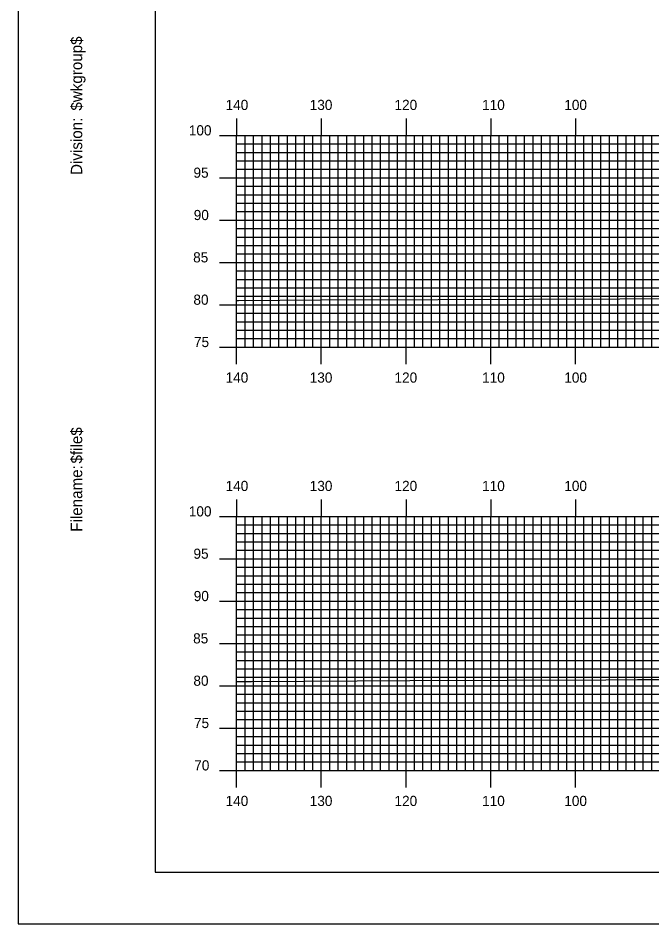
# Model space of a CAD drawing. Extents: x 1757069 to 1757412, y 442591 to 442811.
# Drawn here: x 1757068.8 to 1757143.6, y 442590.5 to 442697.5 of the extents above; entities that cross this region are included whole.
import ezdxf

# ---------------------------------------------------------------- set-up
doc = ezdxf.new("R2010")
doc.units = 0
for name, color, linetype in [('BORDER', 7, 'Continuous'), ('H_V ANNOTATION', 7, 'Continuous'), ('MAJOR', 7, 'Continuous'), ('MINOR', 7, 'Continuous'), ('PLOT BOUNDARY', 7, 'Continuous'), ('S_Roadway_Centerline', 7, 'Continuous')]:
    doc.layers.add(name, color=color, linetype=linetype)

msp = doc.modelspace()

# ---------------------------------------------------------------- linework, layer by layer
at = {"layer": 'BORDER'}
msp.add_lwpolyline([(1757085, 442596.67), (1757405, 442596.67), (1757405, 442806.67), (1757085, 442806.67)], close=True, dxfattribs=at)
at = {"layer": 'MAJOR'}
for p, q in [((1757094.6, 442685.67), (1757094.6, 442683.67)), ((1757104.6, 442685.67), (1757104.6, 442683.67)), ((1757114.6, 442685.67), (1757114.6, 442683.67)), ((1757124.6, 442685.67), (1757124.6, 442683.67)), ((1757134.6, 442685.67), (1757134.6, 442683.67)), ((1757092.59, 442683.67), (1757094.6, 442683.67)), ((1757094.6, 442683.67), (1757374.6, 442683.67)), ((1757094.6, 442658.67), (1757094.6, 442683.67)), ((1757094.6, 442658.67), (1757094.6, 442683.67)), ((1757094.6, 442683.67), (1757374.6, 442683.67)), ((1757104.6, 442658.67), (1757104.6, 442683.67)), ((1757114.6, 442658.67), (1757114.6, 442683.67)), ((1757124.6, 442658.67), (1757124.6, 442683.67)), ((1757134.6, 442658.67), (1757134.6, 442683.67)), ((1757092.59, 442678.67), (1757094.6, 442678.67)), ((1757094.6, 442678.67), (1757374.6, 442678.67)), ((1757092.59, 442673.67), (1757094.6, 442673.67)), ((1757094.6, 442673.67), (1757374.6, 442673.67)), ((1757092.59, 442668.67), (1757094.6, 442668.67)), ((1757094.6, 442668.67), (1757374.6, 442668.67)), ((1757092.59, 442663.67), (1757094.6, 442663.67)), ((1757094.6, 442663.67), (1757374.6, 442663.67)), ((1757092.59, 442658.67), (1757094.6, 442658.67)), ((1757094.6, 442658.67), (1757374.6, 442658.67)), ((1757094.6, 442658.67), (1757374.6, 442658.67)), ((1757094.6, 442656.66), (1757094.6, 442658.67)), ((1757104.6, 442656.66), (1757104.6, 442658.67)), ((1757114.6, 442656.66), (1757114.6, 442658.67)), ((1757124.6, 442656.66), (1757124.6, 442658.67)), ((1757134.6, 442656.66), (1757134.6, 442658.67)), ((1757094.6, 442640.67), (1757094.6, 442638.67)), ((1757104.6, 442640.67), (1757104.6, 442638.67)), ((1757114.6, 442640.67), (1757114.6, 442638.67)), ((1757124.6, 442640.67), (1757124.6, 442638.67)), ((1757134.6, 442640.67), (1757134.6, 442638.67)), ((1757092.59, 442638.67), (1757094.6, 442638.67)), ((1757094.6, 442638.67), (1757374.6, 442638.67)), ((1757094.6, 442608.67), (1757094.6, 442638.67)), ((1757094.6, 442608.67), (1757094.6, 442638.67)), ((1757094.6, 442638.67), (1757374.6, 442638.67)), ((1757104.6, 442608.67), (1757104.6, 442638.67)), ((1757114.6, 442608.67), (1757114.6, 442638.67)), ((1757124.6, 442608.67), (1757124.6, 442638.67)), ((1757134.6, 442608.67), (1757134.6, 442638.67)), ((1757092.59, 442633.67), (1757094.6, 442633.67)), ((1757094.6, 442633.67), (1757374.6, 442633.67)), ((1757092.59, 442628.67), (1757094.6, 442628.67)), ((1757094.6, 442628.67), (1757374.6, 442628.67)), ((1757092.59, 442623.67), (1757094.6, 442623.67)), ((1757094.6, 442623.67), (1757374.6, 442623.67)), ((1757092.59, 442618.67), (1757094.6, 442618.67)), ((1757094.6, 442618.67), (1757374.6, 442618.67)), ((1757092.59, 442613.67), (1757094.6, 442613.67)), ((1757094.6, 442613.67), (1757374.6, 442613.67)), ((1757092.59, 442608.67), (1757094.6, 442608.67)), ((1757094.6, 442608.67), (1757374.6, 442608.67)), ((1757094.6, 442608.67), (1757374.6, 442608.67)), ((1757094.6, 442606.66), (1757094.6, 442608.67)), ((1757104.6, 442606.66), (1757104.6, 442608.67)), ((1757114.6, 442606.66), (1757114.6, 442608.67)), ((1757124.6, 442606.66), (1757124.6, 442608.67)), ((1757134.6, 442606.66), (1757134.6, 442608.67))]:
    msp.add_line(p, q, dxfattribs=at)
at = {"layer": 'MINOR'}
for p, q in [((1757095.6, 442658.67), (1757095.6, 442683.67)), ((1757096.6, 442658.67), (1757096.6, 442683.67)), ((1757097.6, 442658.67), (1757097.6, 442683.67)), ((1757098.6, 442658.67), (1757098.6, 442683.67)), ((1757099.6, 442658.67), (1757099.6, 442683.67)), ((1757100.6, 442658.67), (1757100.6, 442683.67)), ((1757101.6, 442658.67), (1757101.6, 442683.67)), ((1757102.6, 442658.67), (1757102.6, 442683.67)), ((1757103.6, 442658.67), (1757103.6, 442683.67)), ((1757105.6, 442658.67), (1757105.6, 442683.67)), ((1757106.6, 442658.67), (1757106.6, 442683.67)), ((1757107.6, 442658.67), (1757107.6, 442683.67)), ((1757108.6, 442658.67), (1757108.6, 442683.67)), ((1757109.6, 442658.67), (1757109.6, 442683.67)), ((1757110.6, 442658.67), (1757110.6, 442683.67)), ((1757111.6, 442658.67), (1757111.6, 442683.67)), ((1757112.6, 442658.67), (1757112.6, 442683.67)), ((1757113.6, 442658.67), (1757113.6, 442683.67)), ((1757115.6, 442658.67), (1757115.6, 442683.67)), ((1757116.6, 442658.67), (1757116.6, 442683.67)), ((1757117.6, 442658.67), (1757117.6, 442683.67)), ((1757118.6, 442658.67), (1757118.6, 442683.67)), ((1757119.6, 442658.67), (1757119.6, 442683.67)), ((1757120.6, 442658.67), (1757120.6, 442683.67)), ((1757121.6, 442658.67), (1757121.6, 442683.67)), ((1757122.6, 442658.67), (1757122.6, 442683.67)), ((1757123.6, 442658.67), (1757123.6, 442683.67)), ((1757125.6, 442658.67), (1757125.6, 442683.67)), ((1757126.6, 442658.67), (1757126.6, 442683.67)), ((1757127.6, 442658.67), (1757127.6, 442683.67)), ((1757128.6, 442658.67), (1757128.6, 442683.67)), ((1757129.6, 442658.67), (1757129.6, 442683.67)), ((1757130.6, 442658.67), (1757130.6, 442683.67)), ((1757131.6, 442658.67), (1757131.6, 442683.67)), ((1757132.6, 442658.67), (1757132.6, 442683.67)), ((1757133.6, 442658.67), (1757133.6, 442683.67)), ((1757135.6, 442658.67), (1757135.6, 442683.67)), ((1757136.6, 442658.67), (1757136.6, 442683.67)), ((1757137.6, 442658.67), (1757137.6, 442683.67)), ((1757138.6, 442658.67), (1757138.6, 442683.67)), ((1757139.6, 442658.67), (1757139.6, 442683.67)), ((1757140.6, 442658.67), (1757140.6, 442683.67)), ((1757141.6, 442658.67), (1757141.6, 442683.67)), ((1757142.6, 442658.67), (1757142.6, 442683.67)), ((1757143.6, 442658.67), (1757143.6, 442683.67)), ((1757094.6, 442682.67), (1757374.6, 442682.67)), ((1757094.6, 442682.67), (1757096.6, 442682.67)), ((1757094.6, 442681.67), (1757374.6, 442681.67)), ((1757094.6, 442681.67), (1757096.6, 442681.67)), ((1757094.6, 442680.67), (1757374.6, 442680.67)), ((1757094.6, 442680.67), (1757096.6, 442680.67)), ((1757094.6, 442679.67), (1757374.6, 442679.67)), ((1757094.6, 442679.67), (1757096.6, 442679.67)), ((1757094.6, 442677.67), (1757374.6, 442677.67)), ((1757094.6, 442677.67), (1757096.6, 442677.67)), ((1757094.6, 442676.67), (1757374.6, 442676.67)), ((1757094.6, 442676.67), (1757096.6, 442676.67)), ((1757094.6, 442675.67), (1757374.6, 442675.67)), ((1757094.6, 442675.67), (1757096.6, 442675.67)), ((1757094.6, 442674.67), (1757374.6, 442674.67)), ((1757094.6, 442674.67), (1757096.6, 442674.67)), ((1757094.6, 442672.67), (1757374.6, 442672.67)), ((1757094.6, 442672.67), (1757096.6, 442672.67)), ((1757094.6, 442671.67), (1757374.6, 442671.67)), ((1757094.6, 442671.67), (1757096.6, 442671.67)), ((1757094.6, 442670.67), (1757374.6, 442670.67)), ((1757094.6, 442670.67), (1757096.6, 442670.67)), ((1757094.6, 442669.67), (1757374.6, 442669.67)), ((1757094.6, 442669.67), (1757096.6, 442669.67)), ((1757094.6, 442667.67), (1757374.6, 442667.67)), ((1757094.6, 442667.67), (1757096.6, 442667.67)), ((1757094.6, 442666.67), (1757374.6, 442666.67)), ((1757094.6, 442666.67), (1757096.6, 442666.67)), ((1757094.6, 442665.67), (1757374.6, 442665.67)), ((1757094.6, 442665.67), (1757096.6, 442665.67)), ((1757094.6, 442664.67), (1757374.6, 442664.67)), ((1757094.6, 442664.67), (1757096.6, 442664.67)), ((1757094.6, 442662.67), (1757374.6, 442662.67)), ((1757094.6, 442662.67), (1757096.6, 442662.67)), ((1757094.6, 442661.67), (1757374.6, 442661.67)), ((1757094.6, 442661.67), (1757096.6, 442661.67)), ((1757094.6, 442660.67), (1757374.6, 442660.67)), ((1757094.6, 442660.67), (1757096.6, 442660.67)), ((1757094.6, 442659.67), (1757374.6, 442659.67)), ((1757094.6, 442659.67), (1757096.6, 442659.67)), ((1757095.6, 442608.67), (1757095.6, 442638.67)), ((1757096.6, 442608.67), (1757096.6, 442638.67)), ((1757097.6, 442608.67), (1757097.6, 442638.67)), ((1757098.6, 442608.67), (1757098.6, 442638.67)), ((1757099.6, 442608.67), (1757099.6, 442638.67)), ((1757100.6, 442608.67), (1757100.6, 442638.67)), ((1757101.6, 442608.67), (1757101.6, 442638.67)), ((1757102.6, 442608.67), (1757102.6, 442638.67)), ((1757103.6, 442608.67), (1757103.6, 442638.67)), ((1757105.6, 442608.67), (1757105.6, 442638.67)), ((1757106.6, 442608.67), (1757106.6, 442638.67)), ((1757107.6, 442608.67), (1757107.6, 442638.67)), ((1757108.6, 442608.67), (1757108.6, 442638.67)), ((1757109.6, 442608.67), (1757109.6, 442638.67)), ((1757110.6, 442608.67), (1757110.6, 442638.67)), ((1757111.6, 442608.67), (1757111.6, 442638.67)), ((1757112.6, 442608.67), (1757112.6, 442638.67)), ((1757113.6, 442608.67), (1757113.6, 442638.67)), ((1757115.6, 442608.67), (1757115.6, 442638.67)), ((1757116.6, 442608.67), (1757116.6, 442638.67)), ((1757117.6, 442608.67), (1757117.6, 442638.67)), ((1757118.6, 442608.67), (1757118.6, 442638.67)), ((1757119.6, 442608.67), (1757119.6, 442638.67)), ((1757120.6, 442608.67), (1757120.6, 442638.67)), ((1757121.6, 442608.67), (1757121.6, 442638.67)), ((1757122.6, 442608.67), (1757122.6, 442638.67)), ((1757123.6, 442608.67), (1757123.6, 442638.67)), ((1757125.6, 442608.67), (1757125.6, 442638.67)), ((1757126.6, 442608.67), (1757126.6, 442638.67)), ((1757127.6, 442608.67), (1757127.6, 442638.67)), ((1757128.6, 442608.67), (1757128.6, 442638.67)), ((1757129.6, 442608.67), (1757129.6, 442638.67)), ((1757130.6, 442608.67), (1757130.6, 442638.67)), ((1757131.6, 442608.67), (1757131.6, 442638.67)), ((1757132.6, 442608.67), (1757132.6, 442638.67)), ((1757133.6, 442608.67), (1757133.6, 442638.67)), ((1757135.6, 442608.67), (1757135.6, 442638.67)), ((1757136.6, 442608.67), (1757136.6, 442638.67)), ((1757137.6, 442608.67), (1757137.6, 442638.67)), ((1757138.6, 442608.67), (1757138.6, 442638.67)), ((1757139.6, 442608.67), (1757139.6, 442638.67)), ((1757140.6, 442608.67), (1757140.6, 442638.67)), ((1757141.6, 442608.67), (1757141.6, 442638.67)), ((1757142.6, 442608.67), (1757142.6, 442638.67)), ((1757143.6, 442608.67), (1757143.6, 442638.67)), ((1757094.6, 442637.67), (1757374.6, 442637.67)), ((1757094.6, 442637.67), (1757096.6, 442637.67)), ((1757094.6, 442636.67), (1757374.6, 442636.67)), ((1757094.6, 442636.67), (1757096.6, 442636.67)), ((1757094.6, 442635.67), (1757374.6, 442635.67)), ((1757094.6, 442635.67), (1757096.6, 442635.67)), ((1757094.6, 442634.67), (1757374.6, 442634.67)), ((1757094.6, 442634.67), (1757096.6, 442634.67)), ((1757094.6, 442632.67), (1757374.6, 442632.67)), ((1757094.6, 442632.67), (1757096.6, 442632.67)), ((1757094.6, 442631.67), (1757374.6, 442631.67)), ((1757094.6, 442631.67), (1757096.6, 442631.67)), ((1757094.6, 442630.67), (1757374.6, 442630.67)), ((1757094.6, 442630.67), (1757096.6, 442630.67)), ((1757094.6, 442629.67), (1757374.6, 442629.67)), ((1757094.6, 442629.67), (1757096.6, 442629.67)), ((1757094.6, 442627.67), (1757374.6, 442627.67)), ((1757094.6, 442627.67), (1757096.6, 442627.67)), ((1757094.6, 442626.67), (1757374.6, 442626.67)), ((1757094.6, 442626.67), (1757096.6, 442626.67)), ((1757094.6, 442625.67), (1757374.6, 442625.67)), ((1757094.6, 442625.67), (1757096.6, 442625.67)), ((1757094.6, 442624.67), (1757374.6, 442624.67)), ((1757094.6, 442624.67), (1757096.6, 442624.67)), ((1757094.6, 442622.67), (1757374.6, 442622.67)), ((1757094.6, 442622.67), (1757096.6, 442622.67)), ((1757094.6, 442621.67), (1757374.6, 442621.67)), ((1757094.6, 442621.67), (1757096.6, 442621.67)), ((1757094.6, 442620.67), (1757374.6, 442620.67)), ((1757094.6, 442620.67), (1757096.6, 442620.67)), ((1757094.6, 442619.67), (1757374.6, 442619.67)), ((1757094.6, 442619.67), (1757096.6, 442619.67)), ((1757094.6, 442617.67), (1757374.6, 442617.67)), ((1757094.6, 442617.67), (1757096.6, 442617.67)), ((1757094.6, 442616.67), (1757374.6, 442616.67)), ((1757094.6, 442616.67), (1757096.6, 442616.67)), ((1757094.6, 442615.67), (1757374.6, 442615.67)), ((1757094.6, 442615.67), (1757096.6, 442615.67)), ((1757094.6, 442614.67), (1757374.6, 442614.67)), ((1757094.6, 442614.67), (1757096.6, 442614.67)), ((1757094.6, 442612.67), (1757374.6, 442612.67)), ((1757094.6, 442612.67), (1757096.6, 442612.67)), ((1757094.6, 442611.67), (1757374.6, 442611.67)), ((1757094.6, 442611.67), (1757096.6, 442611.67)), ((1757094.6, 442610.67), (1757374.6, 442610.67)), ((1757094.6, 442610.67), (1757096.6, 442610.67)), ((1757094.6, 442609.67), (1757374.6, 442609.67)), ((1757094.6, 442609.67), (1757096.6, 442609.67))]:
    msp.add_line(p, q, dxfattribs=at)
at = {"layer": 'PLOT BOUNDARY'}
msp.add_lwpolyline([(1757068.81, 442590.55), (1757408.81, 442590.55), (1757408.81, 442810.55), (1757068.81, 442810.55)], close=True, dxfattribs=at)
at = {"layer": 'S_Roadway_Centerline'}
for points in [[(1757094.6, 442664.18), (1757094.81, 442664.19), (1757104.62, 442664.24), (1757118.38, 442664.3), (1757139.82, 442664.37), (1757152.51, 442664.44), (1757175.36, 442664.55), (1757195.7, 442664.74), (1757219.61, 442665.15), (1757229.73, 442665.24), (1757247.02, 442664.86), (1757252.08, 442664.77), (1757253.32, 442664.76), (1757254.57, 442664.75), (1757285.8, 442664.81), (1757300.04, 442665.14), (1757329.94, 442665.38), (1757351.56, 442664.86), (1757374.6, 442664.54)], [(1757094.6, 442619.18), (1757096.35, 442619.19), (1757115.03, 442619.28), (1757138.2, 442619.39), (1757141.93, 442619.4), (1757145.49, 442619.42), (1757176.97, 442619.81), (1757201.32, 442619.7), (1757201.96, 442619.71), (1757202.39, 442619.71), (1757227.35, 442619.94), (1757258.33, 442619.75), (1757260.69, 442619.72), (1757265.63, 442619.7), (1757288.04, 442619.12), (1757304.62, 442618.87), (1757310.38, 442618.84), (1757330.15, 442618.65), (1757342.34, 442618.73), (1757360.53, 442618.93), (1757374.6, 442618.78)]]:
    msp.add_lwpolyline(points, dxfattribs=at)

# ---------------------------------------------------------------- texts
at = {"layer": 'BORDER'}
for s, p in [('$wkgroup$', (1757076.37, 442686.6)), ('$wkgroup$', (1757076.37, 442686.6)), ('Division:', (1757076.37, 442679)), ('Division:', (1757076.37, 442679)), ('$file$', (1757076.37, 442644.92)), ('$file$', (1757076.37, 442644.92)), ('Filename:', (1757076.37, 442636.86)), ('Filename:', (1757076.37, 442636.86))]:
    msp.add_text(s, height=1.339, rotation=90, dxfattribs=at).set_placement(p)
at = {"layer": 'H_V ANNOTATION'}
for s, p in [('140', (1757093.3, 442686.67)), ('130', (1757103.23, 442686.67)), ('120', (1757113.24, 442686.67)), ('110', (1757123.58, 442686.67)), ('100', (1757133.28, 442686.67)), ('100', (1757088.96, 442683.67)), ('95', (1757089.51, 442678.67)), ('90', (1757089.54, 442673.67)), ('85', (1757089.47, 442668.67)), ('80', (1757089.5, 442663.67)), ('75', (1757089.57, 442658.67)), ('140', (1757093.3, 442654.47)), ('130', (1757103.23, 442654.47)), ('120', (1757113.24, 442654.47)), ('110', (1757123.58, 442654.47)), ('100', (1757133.28, 442654.47)), ('140', (1757093.3, 442641.67)), ('130', (1757103.23, 442641.67)), ('120', (1757113.24, 442641.67)), ('110', (1757123.58, 442641.67)), ('100', (1757133.28, 442641.67)), ('100', (1757088.96, 442638.67)), ('95', (1757089.51, 442633.67)), ('90', (1757089.54, 442628.67)), ('85', (1757089.47, 442623.67)), ('80', (1757089.5, 442618.67)), ('75', (1757089.57, 442613.67)), ('70', (1757089.6, 442608.67)), ('140', (1757093.3, 442604.47)), ('130', (1757103.23, 442604.47)), ('120', (1757113.24, 442604.47)), ('110', (1757123.58, 442604.47)), ('100', (1757133.28, 442604.47))]:
    msp.add_text(s, height=1.2, dxfattribs=at).set_placement(p)
at = {"layer": 'MAJOR'}
for p in [(1757094.59, 442658.67), (1757094.59, 442608.67)]:
    msp.add_text('-', height=0.012, dxfattribs=at).set_placement(p)

doc.saveas('drawing.dxf')
